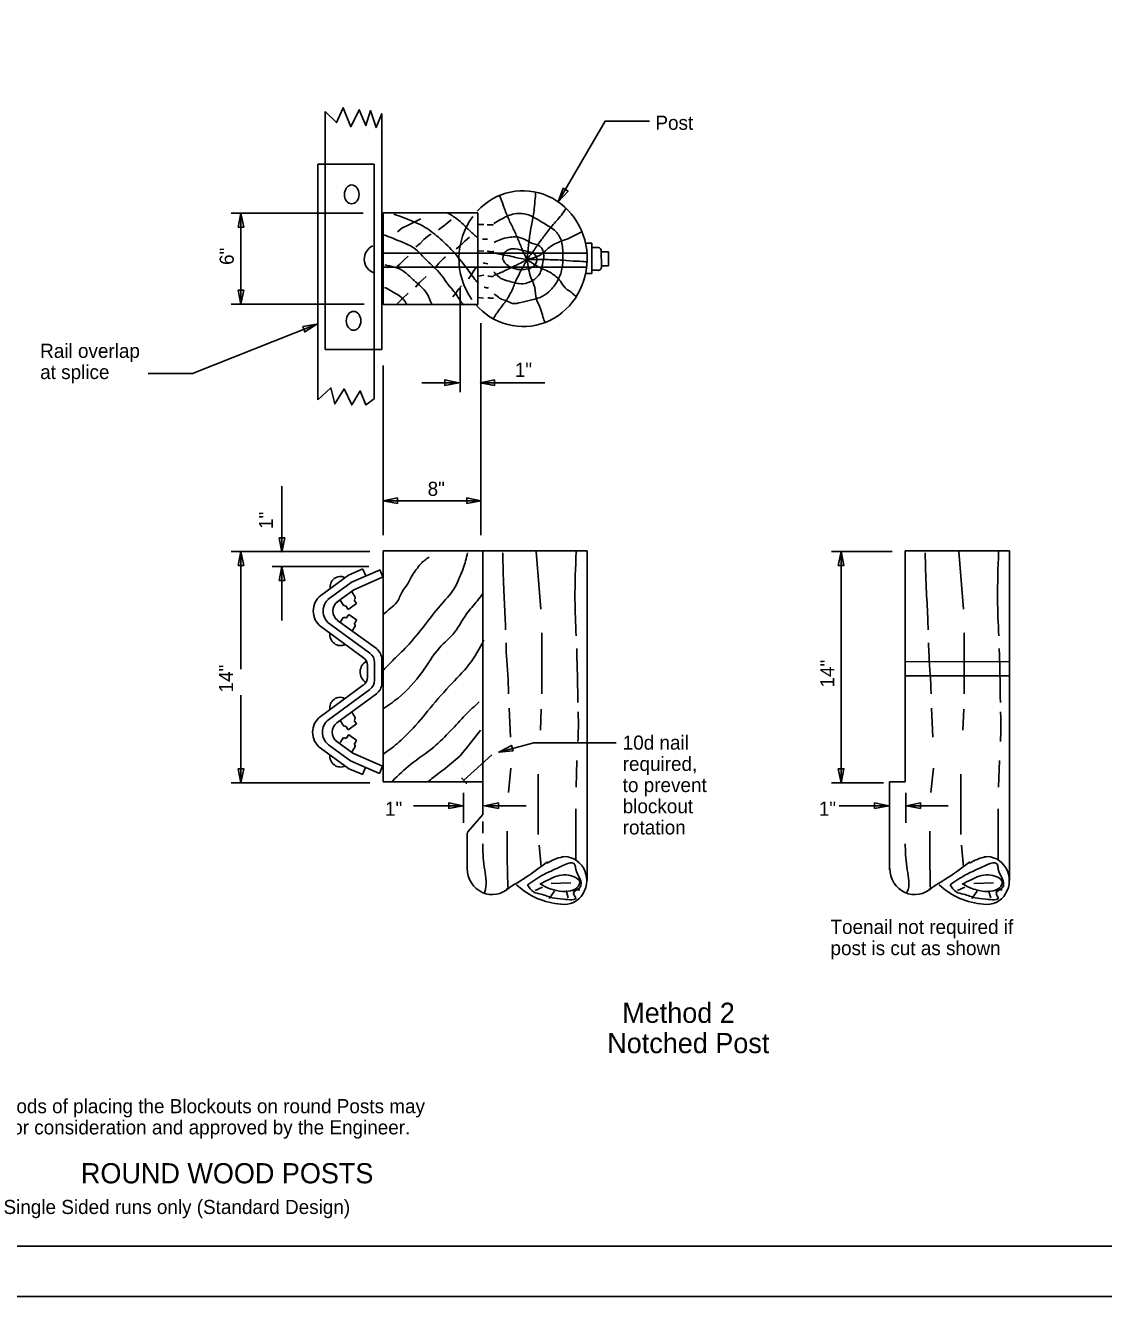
# Model space of a CAD drawing. Extents: x 0 to 34, y 0 to 22.
# Drawn here: x 8.69 to 19.37, y 0 to 12.6 of the extents above; entities that cross this region are included whole.
import ezdxf

# ---------------------------------------------------------------- set-up
doc = ezdxf.new("R2010")
doc.units = 0
for name, color, linetype in [('SH_Border', 7, 'Continuous'), ('SH_Cut_Line', 7, 'Continuous'), ('ST_Details', 7, 'Continuous'), ('ST_Text', 7, 'Continuous')]:
    doc.layers.add(name, color=color, linetype=linetype)

msp = doc.modelspace()

# ---------------------------------------------------------------- linework, layer by layer
at = {"layer": 'SH_Border'}
msp.add_lwpolyline([(1.5, 21.5), (33.5, 21.5), (33.5, 0.5), (1.5, 0.5)], close=True, dxfattribs=at)
at = {"layer": 'SH_Cut_Line'}
msp.add_lwpolyline([(0, 0), (34, 0), (34, 22), (0, 22)], close=True, dxfattribs=at)
at = {"layer": 'ST_Details'}
for p, q in [((11.658, 11.741), (11.658, 11.227)), ((12.218, 11.721), (12.218, 9.383)), ((11.583, 11.221), (11.583, 8.885)), ((11.583, 11.221), (12.143, 11.221)), ((11.658, 11.221), (11.658, 9.383)), ((12.143, 11.221), (12.143, 8.895)), ((12.232, 10.739), (13.171, 10.739)), ((12.232, 9.829), (12.232, 10.739)), ((13.17, 9.829), (13.17, 10.739)), ((13.216, 10.476), (13.266, 10.478)), ((12.225, 10.339), (14.248, 10.339)), ((13.174, 10.357), (13.23, 10.361)), ((14.239, 10.437), (14.299, 10.437)), ((14.251, 10.342), (14.251, 10.342)), ((14.299, 10.136), (14.299, 10.437)), ((14.299, 10.394), (14.367, 10.394)), ((14.393, 10.36), (14.394, 10.206)), ((14.393, 10.353), (14.464, 10.353)), ((14.464, 10.213), (14.464, 10.353)), ((14.394, 10.213), (14.464, 10.213)), ((12.225, 10.2), (14.248, 10.2)), ((13.174, 10.111), (13.228, 10.12)), ((14.239, 10.136), (14.299, 10.136)), ((14.299, 10.17), (14.358, 10.17)), ((12.232, 9.829), (13.17, 9.829)), ((13.17, 9.899), (13.226, 9.892)), ((11.658, 9.383), (12.143, 9.383)), ((12.143, 9.383), (12.218, 9.383)), ((12.232, 7.389), (12.232, 5.099)), ((12.232, 7.389), (14.252, 7.389)), ((13.218, 7.389), (13.218, 4.777)), ((13.748, 7.383), (13.795, 6.81)), ((14.252, 4.122), (14.252, 7.389)), ((17.405, 7.389), (17.405, 5.099)), ((18.439, 7.389), (17.405, 7.389)), ((17.935, 7.383), (17.982, 6.81)), ((18.439, 4.122), (18.439, 7.389)), ((11.887, 7.147), (12.031, 7.21)), ((11.912, 7.074), (12.201, 7.201)), ((12.059, 7.14), (12.031, 7.209)), ((12.227, 7.13), (12.2, 7.2)), ((11.887, 7.147), (11.614, 6.947)), ((11.914, 7.076), (11.684, 6.907)), ((11.941, 7.004), (12.231, 7.13)), ((11.94, 7.003), (11.773, 6.881)), ((11.951, 6.936), (11.921, 6.984)), ((11.835, 6.854), (11.806, 6.9)), ((11.884, 6.807), (11.861, 6.844)), ((11.884, 6.808), (11.966, 6.866)), ((11.966, 6.866), (11.943, 6.902)), ((12.164, 6.42), (11.78, 6.7)), ((11.805, 6.681), (11.837, 6.731)), ((11.865, 6.722), (11.89, 6.76)), ((11.969, 6.703), (11.89, 6.76)), ((11.944, 6.664), (11.968, 6.702)), ((12.038, 6.33), (11.615, 6.638)), ((12.101, 6.375), (11.697, 6.669)), ((11.923, 6.595), (11.954, 6.644)), ((13.803, 6.577), (13.803, 5.972)), ((17.989, 6.577), (17.989, 5.972)), ((12.218, 6.079), (12.218, 6.312)), ((12.076, 6.138), (12.076, 6.253)), ((12.147, 6.109), (12.147, 6.282)), ((12.147, 6.19), (12.147, 6.201)), ((17.405, 6.29), (18.44, 6.293)), ((12.038, 6.061), (11.608, 5.746)), ((17.405, 6.149), (18.439, 6.152)), ((12.101, 6.016), (11.69, 5.715)), ((12.165, 5.971), (11.773, 5.684)), ((13.479, 5.83), (13.492, 5.542)), ((13.798, 5.822), (13.789, 5.613)), ((17.666, 5.83), (17.678, 5.542)), ((17.984, 5.822), (17.975, 5.613)), ((11.835, 5.661), (11.806, 5.707)), ((11.884, 5.615), (11.966, 5.674)), ((11.951, 5.744), (11.921, 5.791)), ((11.966, 5.674), (11.943, 5.709)), ((11.884, 5.615), (11.861, 5.651)), ((11.865, 5.529), (11.89, 5.568)), ((11.969, 5.51), (11.89, 5.567)), ((11.888, 5.233), (11.608, 5.437)), ((11.908, 5.309), (11.691, 5.468)), ((11.931, 5.384), (11.773, 5.499)), ((11.805, 5.489), (11.837, 5.539)), ((11.923, 5.402), (11.954, 5.451)), ((11.944, 5.471), (11.968, 5.509)), ((12.196, 5.184), (11.907, 5.31)), ((11.931, 5.385), (12.224, 5.257)), ((12.629, 5.363), (12.629, 5.363)), ((12.994, 5.358), (12.846, 5.231)), ((13.029, 5.113), (13.309, 5.367)), ((14.151, 5.312), (14.143, 5.046)), ((18.338, 5.312), (18.33, 5.046)), ((11.885, 5.234), (12.029, 5.172)), ((12.028, 5.172), (12.057, 5.244)), ((12.195, 5.184), (12.224, 5.257)), ((13.497, 5.237), (13.472, 4.995)), ((13.769, 5.175), (13.769, 4.578)), ((17.684, 5.237), (17.659, 4.995)), ((17.956, 5.175), (17.956, 4.578)), ((12.232, 5.099), (13.224, 5.099)), ((13.06, 5.079), (13.009, 5.14)), ((17.25, 4.307), (17.25, 5.099)), ((17.25, 5.099), (17.405, 5.099)), ((13.218, 4.777), (13.07, 4.606)), ((13.218, 4.706), (13.218, 4.592)), ((13.064, 4.307), (13.064, 4.594)), ((13.07, 4.599), (13.07, 4.606)), ((13.776, 4.472), (13.796, 4.258)), ((17.963, 4.472), (17.983, 4.258)), ((13.064, 4.229), (13.064, 4.307)), ((17.25, 4.229), (17.25, 4.307)), ((13.736, 4.023), (13.81, 4.058)), ((13.897, 4.094), (14.092, 4.101)), ((14.179, 4.108), (14.173, 4.143)), ((17.922, 4.023), (17.996, 4.058)), ((18.083, 4.094), (18.278, 4.101)), ((18.366, 4.108), (18.36, 4.143)), ((13.877, 3.945), (13.93, 4.016)), ((14.065, 3.952), (14.045, 4.023)), ((14.18, 4.029), (14.099, 4.022)), ((14.099, 4.022), (14.139, 4.023)), ((18.063, 3.945), (18.117, 4.016)), ((18.251, 3.952), (18.231, 4.023)), ((18.366, 4.029), (18.286, 4.022)), ((18.286, 4.022), (18.325, 4.023))]:
    msp.add_line(p, q, dxfattribs=at)
for points in [[(11.658, 11.741), (11.77, 11.632), (11.836, 11.78), (11.91, 11.592), (11.994, 11.76), (12.06, 11.602), (12.106, 11.751), (12.162, 11.583), (12.218, 11.721)], [(12.372, 10.549), (12.418, 10.586), (12.478, 10.617), (12.552, 10.651), (12.604, 10.679)], [(12.779, 10.571), (12.833, 10.611), (12.867, 10.635), (12.904, 10.668)], [(12.556, 10.401), (12.598, 10.436), (12.635, 10.474), (12.687, 10.516), (12.708, 10.527)], [(12.955, 10.381), (12.998, 10.416), (13.042, 10.458), (13.088, 10.496)], [(12.37, 10.206), (12.397, 10.231), (12.435, 10.27), (12.478, 10.31)], [(12.752, 10.2), (12.783, 10.239), (12.825, 10.281), (12.85, 10.301)], [(12.552, 10.003), (12.593, 10.049), (12.658, 10.109)], [(13.076, 10.085), (13.103, 10.12), (13.126, 10.16), (13.153, 10.197)], [(12.923, 9.906), (12.952, 9.943), (12.978, 9.981), (13.009, 10.016)], [(12.359, 9.826), (12.422, 9.888), (12.478, 9.941)], [(11.583, 8.885), (11.714, 9.003), (11.752, 8.845), (11.845, 8.994), (11.92, 8.835), (12.004, 8.974), (12.06, 8.835), (12.143, 8.895)]]:
    msp.add_lwpolyline(points, dxfattribs=at)
for centre in [(11.92, 10.921), (11.938, 9.668)]:
    msp.add_ellipse(centre, major_axis=(0.0005, 0.0936), ratio=0.773782, dxfattribs=at)
for centre, major_axis, start_param, end_param in [((13.618, 10.284), (0, 0.673), 2.303639, 7.079119), ((13.618, 10.284), (0, 0.673), 0.900881, 2.214399), ((12.178, 10.279), (0, -0.141), 3.514867, 5.984065), ((14.364, 10.364), (0, 0.03), 4.574534, 6.237266), ((14.366, 10.365), (0, -0.0298), 1.431351, 1.439211), ((14.363, 10.201), (0, -0.0326), 6.093782, 8.002272), ((11.807, 7.028), (0, -0.107), 2.687211, 4.851441), ((11.715, 6.793), (0, -0.187), 3.747084, 5.680264), ((11.935, 6.924), (0, 0.0198), 3.70437, 5.352473), ((11.778, 6.793), (0, -0.15), 3.747137, 5.680324), ((11.84, 6.793), (0, -0.112), 3.747102, 5.680297), ((11.848, 6.865), (0, -0.0195), 5.247458, 6.879592), ((11.85, 6.708), (0, 0.021), 5.452301, 7.118326), ((11.81, 6.565), (0, -0.115), 4.640651, 6.714317), ((11.935, 6.646), (0, 0.021), 4.196406, 5.73538), ((11.988, 6.253), (0, 0.0937), 4.712389, 5.680377), ((12.041, 6.282), (0, 0.112), 4.712389, 5.68034), ((12.094, 6.312), (0, 0.131), 4.712389, 5.680267), ((12.117, 6.189), (0, -0.12), 3.613765, 5.74142), ((11.988, 6.138), (0, -0.0937), 0.605563, 1.570796), ((12.041, 6.109), (0, -0.112), 0.605651, 1.570796), ((12.094, 6.079), (0, -0.131), 0.605566, 1.570796), ((11.804, 5.831), (0, -0.107), 2.687211, 4.851441), ((11.709, 5.592), (0, -0.187), 3.747091, 5.68028), ((11.771, 5.592), (0, -0.15), 3.747115, 5.680355), ((11.833, 5.592), (0, -0.112), 3.747102, 5.680258), ((11.935, 5.731), (0, 0.0198), 3.70437, 5.352473), ((11.848, 5.672), (0, -0.0195), 5.247458, 6.879592), ((11.85, 5.515), (0, 0.021), 5.452301, 7.118326), ((11.935, 5.453), (0, 0.021), 4.196406, 5.73538), ((11.81, 5.362), (0, -0.115), 4.640651, 6.714317), ((14.097, 3.856), (0, 0.508), 0.179437, 0.530353), ((14.025, 4.122), (0, 0.237), 2.997307, 6.40595), ((18.284, 3.856), (0, 0.508), 0.179437, 0.530353), ((18.212, 4.122), (0, 0.237), 2.997307, 6.40595), ((13.313, 4.247), (0, -0.264), 4.726587, 7.018323), ((17.5, 4.247), (0, -0.264), 4.726587, 7.018323), ((14.039, 4.667), (0, -0.78), 5.564047, 6.222034), ((18.226, 4.667), (0, -0.78), 5.564047, 6.222034)]:
    msp.add_ellipse(centre, major_axis=major_axis, ratio=0.944544, start_param=start_param, end_param=end_param, dxfattribs=at)
for points in [[(13.654, 10.279), (13.617, 10.359), (13.573, 10.465), (13.527, 10.569), (13.479, 10.668), (13.435, 10.777), (13.422, 10.814), (13.385, 10.909)], [(13.656, 10.284), (13.667, 10.374), (13.683, 10.505), (13.704, 10.629), (13.729, 10.781), (13.738, 10.88), (13.744, 10.945)], [(12.337, 10.726), (12.439, 10.688), (12.629, 10.606), (12.779, 10.496), (12.923, 10.357), (13.057, 10.193), (13.153, 10.063), (13.173, 10.038)], [(12.867, 10.739), (12.961, 10.679), (13.09, 10.56), (13.171, 10.488)], [(13.328, 10.633), (13.395, 10.671), (13.514, 10.724), (13.658, 10.721), (13.823, 10.635), (13.942, 10.553), (13.999, 10.456), (14.011, 10.317), (14.003, 10.182), (13.959, 10.065), (13.892, 9.974), (13.811, 9.912), (13.706, 9.877), (13.596, 9.85), (13.514, 9.841), (13.45, 9.868), (13.399, 9.886), (13.349, 9.923), (13.33, 9.937)], [(13.658, 10.281), (13.706, 10.341), (13.777, 10.441), (13.842, 10.529), (13.928, 10.635), (13.972, 10.686), (14.02, 10.746), (14.042, 10.783)], [(13.174, 10.622), (13.224, 10.622), (13.23, 10.622)], [(13.262, 10.621), (13.301, 10.62), (13.326, 10.622)], [(12.243, 10.52), (12.422, 10.447), (12.535, 10.39), (12.671, 10.259), (12.771, 10.166), (12.89, 10.01), (12.973, 9.903), (13.021, 9.835), (13.03, 9.828)], [(13.33, 10.445), (13.397, 10.474), (13.472, 10.494), (13.606, 10.487), (13.702, 10.438), (13.786, 10.405), (13.823, 10.312), (13.813, 10.248), (13.792, 10.153), (13.719, 10.071), (13.614, 10.036), (13.481, 10.06), (13.399, 10.089), (13.351, 10.127), (13.328, 10.153)], [(13.66, 10.279), (13.779, 10.317), (13.898, 10.41), (14.04, 10.474), (14.122, 10.509), (14.201, 10.551)], [(13.262, 10.358), (13.289, 10.354), (13.328, 10.354)], [(13.654, 10.277), (13.577, 10.288), (13.506, 10.306), (13.414, 10.323), (13.356, 10.337), (13.335, 10.343)], [(13.414, 10.277), (13.429, 10.334), (13.462, 10.368), (13.541, 10.381), (13.637, 10.361), (13.733, 10.326), (13.754, 10.266), (13.702, 10.195), (13.631, 10.177), (13.546, 10.182), (13.481, 10.208), (13.437, 10.244), (13.418, 10.277)], [(12.248, 10.222), (12.426, 10.164), (12.512, 10.091), (12.618, 9.996), (12.677, 9.919), (12.712, 9.841), (12.723, 9.826)], [(13.221, 10.237), (13.239, 10.239), (13.268, 10.232)], [(13.66, 10.277), (13.614, 10.197), (13.587, 10.146), (13.539, 10.049), (13.518, 9.996), (13.46, 9.883), (13.439, 9.853), (13.418, 9.828), (13.389, 9.786), (13.36, 9.749), (13.341, 9.718), (13.328, 9.698), (13.322, 9.693)], [(13.654, 10.279), (13.61, 10.248), (13.543, 10.217), (13.435, 10.164), (13.358, 10.129), (13.328, 10.118)], [(13.654, 10.277), (13.769, 10.204), (13.898, 10.14), (13.988, 10.06), (14.053, 9.979), (14.095, 9.952), (14.132, 9.919), (14.149, 9.91)], [(13.658, 10.277), (13.827, 10.275), (13.984, 10.27), (14.114, 10.261), (14.199, 10.257), (14.249, 10.253)], [(13.658, 10.277), (13.673, 10.182), (13.696, 10.098), (13.733, 9.998), (13.75, 9.883), (13.792, 9.788), (13.815, 9.707), (13.836, 9.649)], [(13.269, 10.111), (13.27, 10.111), (13.32, 10.109), (13.326, 10.111)], [(12.246, 10), (12.382, 9.921), (12.433, 9.879), (12.468, 9.828)], [(13.232, 10.002), (13.257, 9.996), (13.274, 9.998)], [(13.27, 9.897), (13.31, 9.892), (13.324, 9.895)], [(12.233, 6.758), (12.302, 6.819), (12.368, 6.881), (12.419, 6.984), (12.48, 7.069), (12.52, 7.146), (12.56, 7.204), (12.604, 7.261), (12.687, 7.327)], [(12.237, 6.211), (12.335, 6.311), (12.488, 6.465), (12.662, 6.677), (12.815, 6.869), (12.945, 7.031), (12.989, 7.127), (13.025, 7.215), (13.068, 7.368)], [(13.416, 7.37), (13.427, 7.018), (13.44, 6.733), (13.444, 6.606)], [(14.144, 7.378), (14.132, 6.911), (14.144, 6.548)], [(17.602, 7.37), (17.613, 7.018), (17.627, 6.733), (17.631, 6.606)], [(18.33, 7.378), (18.319, 6.911), (18.331, 6.548)], [(12.226, 5.819), (12.379, 5.931), (12.618, 6.188), (12.789, 6.427), (12.942, 6.585), (13.058, 6.765), (13.163, 6.892), (13.219, 6.966)], [(13.23, 6.504), (13.082, 6.262), (12.887, 6.048), (12.672, 5.799), (12.477, 5.579), (12.336, 5.451), (12.228, 5.372)], [(13.449, 6.478), (13.453, 6.349), (13.474, 5.979), (13.474, 5.972)], [(17.635, 6.478), (17.64, 6.349), (17.66, 5.979), (17.66, 5.972)], [(14.149, 6.42), (14.152, 6.328), (14.161, 5.887)], [(18.336, 6.42), (18.339, 6.328), (18.347, 5.887)], [(13.183, 5.892), (13.048, 5.764), (12.9, 5.607), (12.732, 5.444), (12.504, 5.273), (12.323, 5.108)], [(14.163, 5.795), (14.166, 5.638), (14.161, 5.5)], [(18.349, 5.795), (18.352, 5.638), (18.347, 5.5)], [(12.994, 5.358), (13.051, 5.427), (13.197, 5.611)], [(12.673, 5.1), (12.782, 5.185), (12.846, 5.231)], [(14.139, 4.833), (14.139, 4.62), (14.139, 4.371), (14.139, 4.328)], [(18.326, 4.833), (18.326, 4.62), (18.326, 4.371), (18.326, 4.328)], [(13.46, 4.613), (13.46, 4.443), (13.467, 4.058)], [(17.647, 4.613), (17.647, 4.443), (17.653, 4.058)], [(13.218, 4.485), (13.218, 4.464), (13.238, 4.229), (13.238, 4.009), (13.232, 3.994)], [(17.405, 4.485), (17.405, 4.464), (17.425, 4.229), (17.425, 4.009), (17.418, 3.994)], [(13.453, 4.037), (13.641, 4.151), (13.86, 4.307)], [(13.662, 4.08), (13.816, 4.179), (13.951, 4.243), (14.132, 4.279), (14.139, 4.235), (14.18, 4.143), (14.18, 4.051), (14.119, 3.994), (14.139, 3.952), (14.018, 3.938), (13.91, 3.952), (13.796, 3.987), (13.722, 4.009), (13.662, 4.08)], [(17.64, 4.037), (17.828, 4.151), (18.046, 4.307)], [(17.848, 4.08), (18.003, 4.179), (18.137, 4.243), (18.319, 4.279), (18.326, 4.235), (18.366, 4.143), (18.366, 4.051), (18.306, 3.994), (18.325, 3.952), (18.204, 3.938), (18.097, 3.952), (17.983, 3.987), (17.909, 4.009), (17.848, 4.08)], [(13.783, 4.087), (13.87, 4.13), (13.951, 4.165), (14.045, 4.179), (14.125, 4.158), (14.179, 4.108), (14.152, 4.051), (14.065, 4.016), (13.951, 4.023), (13.877, 4.044), (13.789, 4.087)], [(17.969, 4.087), (18.057, 4.13), (18.137, 4.165), (18.231, 4.179), (18.312, 4.158), (18.366, 4.108), (18.339, 4.051), (18.251, 4.016), (18.137, 4.023), (18.063, 4.044), (17.976, 4.087)]]:
    msp.add_spline(points, degree=3, dxfattribs=at)
at = {"layer": 'ST_Text'}
for p, q in [((10.727, 10.736), (12.033, 10.736)), ((10.822, 10.736), (10.822, 10.159)), ((10.822, 10.159), (10.822, 9.832)), ((12.993, 9.995), (12.993, 8.96)), ((10.727, 9.832), (12.042, 9.832)), ((13.2, 9.644), (13.2, 7.969)), ((12.232, 9.227), (12.232, 7.969)), ((12.616, 9.054), (12.981, 9.054)), ((13.194, 9.054), (13.835, 9.054)), ((11.228, 8.03), (11.228, 7.377)), ((12.232, 7.969), (12.232, 7.544)), ((13.2, 7.969), (13.2, 7.544)), ((12.233, 7.886), (13.2, 7.886)), ((10.727, 7.384), (12.101, 7.384)), ((10.822, 7.384), (10.822, 6.217)), ((16.674, 7.384), (17.274, 7.384)), ((16.769, 7.384), (16.769, 6.217)), ((11.133, 7.234), (12.091, 7.234)), ((11.228, 7.234), (11.228, 6.698)), ((16.769, 6.217), (16.769, 5.959)), ((10.822, 5.959), (10.822, 5.09)), ((16.769, 5.959), (16.769, 5.09)), ((13.376, 5.395), (13.726, 5.488)), ((13.726, 5.488), (14.54, 5.488)), ((10.727, 5.09), (11.826, 5.09)), ((11.826, 5.09), (12.101, 5.09)), ((16.674, 5.09), (16.999, 5.09)), ((16.999, 5.09), (17.188, 5.09)), ((13.028, 4.991), (13.028, 4.694)), ((17.411, 4.991), (17.411, 4.694)), ((12.532, 4.864), (13.021, 4.864)), ((13.234, 4.864), (13.649, 4.864)), ((16.751, 4.864), (17.241, 4.864)), ((17.416, 4.864), (17.83, 4.864))]:
    msp.add_line(p, q, dxfattribs=at)
for points in [[(13.965, 10.848), (14.43, 11.647), (14.87, 11.647)], [(11.575, 9.635), (10.342, 9.145), (9.902, 9.145)]]:
    msp.add_lwpolyline(points, dxfattribs=at)
for points in [[(14.015, 10.982), (13.965, 10.848), (14.063, 10.952)], [(10.794, 10.596), (10.822, 10.736), (10.85, 10.596)], [(10.794, 9.972), (10.822, 9.832), (10.85, 9.972)], [(11.434, 9.611), (11.575, 9.635), (11.454, 9.559)], [(12.841, 9.026), (12.981, 9.054), (12.841, 9.082)], [(13.334, 9.026), (13.194, 9.054), (13.334, 9.082)], [(12.373, 7.858), (12.233, 7.886), (12.373, 7.914)], [(13.06, 7.858), (13.2, 7.886), (13.06, 7.914)], [(11.2, 7.517), (11.228, 7.377), (11.256, 7.517)], [(10.794, 7.244), (10.822, 7.384), (10.85, 7.244)], [(16.741, 7.244), (16.769, 7.384), (16.797, 7.244)], [(11.2, 7.094), (11.228, 7.234), (11.256, 7.094)], [(13.518, 5.407), (13.376, 5.395), (13.503, 5.461)], [(10.794, 5.23), (10.822, 5.09), (10.85, 5.23)], [(16.741, 5.23), (16.769, 5.09), (16.797, 5.23)], [(12.881, 4.836), (13.021, 4.864), (12.881, 4.892)], [(13.374, 4.836), (13.234, 4.864), (13.374, 4.892)], [(17.101, 4.836), (17.241, 4.864), (17.101, 4.892)], [(17.556, 4.836), (17.416, 4.864), (17.556, 4.892)]]:
    msp.add_lwpolyline(points, close=True, dxfattribs=at)

# ---------------------------------------------------------------- texts
for s, rotation, p in [('Post', 360, (14.929, 11.561)), ('6" ', 90, (10.751, 10.222)), ('Rail overlap', 360, (8.833, 9.301)), ('at splice', 360, (8.833, 9.091)), ('1"', 360, (13.536, 9.113)), ('8" ', 360, (12.672, 7.934)), ('1" ', 90, (11.14, 7.606)), ('14" ', 90, (16.702, 6.035)), ('14" ', 90, (10.744, 5.986)), ('10d nail ', 360, (14.605, 5.419)), ('required, ', 360, (14.605, 5.209)), ('to prevent ', 360, (14.605, 4.999)), ('blockout ', 360, (14.605, 4.789)), ('1"', 360, (12.25, 4.764)), ('1" ', 360, (16.548, 4.764)), ('rotation', 360, (14.605, 4.579)), ('Toenail not required if', 360, (16.664, 3.593)), ('post is cut as shown', 360, (16.664, 3.383)), ('Alternate methods of placing the Blockouts on round Posts may', 360, (7.38, 1.817)), ('be submitted for consideration and approved by the Engineer.', 360, (7.38, 1.607)), ('Single Sided runs only (Standard Design)', 360, (8.47, 0.818))]:
    msp.add_text(s, height=0.14, rotation=rotation, dxfattribs=at).set_placement(p)
for s, p in [('  Method 2', (14.452, 2.712)), ('Notched Post', (14.452, 2.412)), ('ROUND WOOD POSTS', (9.237, 1.122))]:
    msp.add_text(s, height=0.2, dxfattribs=at).set_placement(p)

doc.saveas('drawing.dxf')
